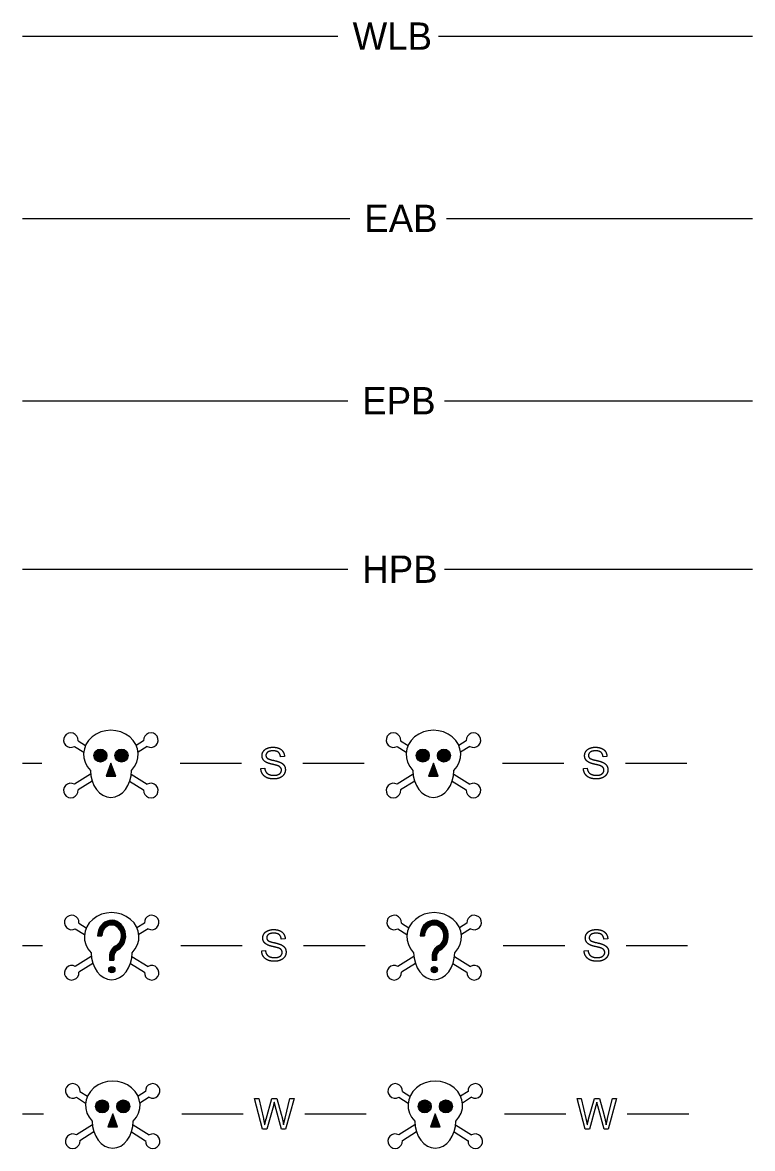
# Model space of a CAD drawing. Extents: x 811137 to 813186, y 647386 to 648494.
# Drawn here: x 811460.4 to 811541.1, y 647953.1 to 648077.7 of the extents above; entities that cross this region are included whole.
import ezdxf

# ---------------------------------------------------------------- set-up
doc = ezdxf.new("R2010")
doc.units = 0
doc.layers.add('Sheet_Symbology', color=7, linetype='Continuous')

msp = doc.modelspace()

# ---------------------------------------------------------------- linework, layer by layer
at = {"layer": 'Sheet_Symbology'}
for p, q in [((811460.36, 648076.23), (811495.24, 648076.23)), ((811506.34, 648076.23), (811541.07, 648076.23)), ((811460.36, 648056.06), (811496.54, 648056.06)), ((811507.23, 648056.06), (811541.07, 648056.06)), ((811460.36, 648035.88), (811496.31, 648035.88)), ((811507.01, 648035.88), (811541.07, 648035.88)), ((811460.36, 648017.25), (811496.31, 648017.25)), ((811507.01, 648017.25), (811541.07, 648017.25)), ((811466.51, 647998.26), (811467.33, 647997.74)), ((811473.75, 647998.26), (811472.93, 647997.74)), ((811502.17, 647998.26), (811503, 647997.74)), ((811509.41, 647998.26), (811508.59, 647997.74)), ((811466.1, 647997.62), (811467.12, 647996.98)), ((811474.15, 647997.62), (811473.13, 647996.98)), ((811501.77, 647997.62), (811502.79, 647996.98)), ((811509.82, 647997.62), (811508.8, 647996.98)), ((811460.36, 647995.78), (811462.48, 647995.78)), ((811477.77, 647995.78), (811484.56, 647995.78)), ((811489.32, 647996.52), (811488.89, 647996.49)), ((811491.36, 647995.78), (811498.15, 647995.78)), ((811513.44, 647995.78), (811520.23, 647995.78)), ((811524.98, 647996.52), (811524.55, 647996.49)), ((811527.02, 647995.78), (811533.82, 647995.78)), ((811467.88, 647994.57), (811466.1, 647993.45)), ((811470.13, 647995.53), (811470.13, 647995.53)), ((811472.38, 647994.57), (811474.15, 647993.45)), ((811486.71, 647995.18), (811487.14, 647995.21)), ((811503.55, 647994.57), (811501.77, 647993.45)), ((811505.79, 647995.53), (811505.79, 647995.53)), ((811508.04, 647994.57), (811509.82, 647993.45)), ((811522.38, 647995.18), (811522.8, 647995.21)), ((811468.05, 647993.78), (811466.51, 647992.81)), ((811472.2, 647993.78), (811473.75, 647992.81)), ((811503.72, 647993.78), (811502.17, 647992.81)), ((811507.87, 647993.78), (811509.41, 647992.81)), ((811466.19, 647977.44), (811467.2, 647976.8)), ((811466.59, 647978.08), (811467.41, 647977.56)), ((811473.83, 647978.08), (811473.01, 647977.56)), ((811474.24, 647977.44), (811473.22, 647976.8)), ((811501.85, 647977.44), (811502.87, 647976.8)), ((811502.26, 647978.08), (811503.08, 647977.56)), ((811509.5, 647978.08), (811508.67, 647977.56)), ((811509.9, 647977.44), (811508.88, 647976.8)), ((811468.65, 647976.66), (811469.13, 647976.66)), ((811489.4, 647976.35), (811488.97, 647976.31)), ((811504.32, 647976.66), (811504.8, 647976.66)), ((811525.07, 647976.35), (811524.64, 647976.31)), ((811460.36, 647975.6), (811462.57, 647975.6)), ((811470.21, 647975.6), (811470.21, 647975.6)), ((811477.85, 647975.6), (811484.65, 647975.6)), ((811486.8, 647975), (811487.22, 647975.03)), ((811491.44, 647975.6), (811498.23, 647975.6)), ((811505.88, 647975.6), (811505.88, 647975.6)), ((811513.52, 647975.6), (811520.31, 647975.6)), ((811522.46, 647975), (811522.89, 647975.03)), ((811527.11, 647975.6), (811533.9, 647975.6)), ((811467.96, 647974.39), (811466.19, 647973.27)), ((811468.13, 647973.6), (811466.59, 647972.63)), ((811469.97, 647974.38), (811469.97, 647973.96)), ((811469.97, 647973.96), (811470.45, 647973.96)), ((811470.04, 647974.38), (811470.04, 647973.96)), ((811470.11, 647974.38), (811470.11, 647973.96)), ((811470.18, 647974.38), (811470.18, 647973.96)), ((811470.25, 647974.38), (811470.25, 647973.96)), ((811470.31, 647974.38), (811470.31, 647973.96)), ((811470.38, 647974.38), (811470.38, 647973.96)), ((811470.45, 647974.38), (811470.45, 647973.96)), ((811472.29, 647973.6), (811473.83, 647972.63)), ((811472.46, 647974.39), (811474.24, 647973.27)), ((811503.63, 647974.39), (811501.85, 647973.27)), ((811503.8, 647973.6), (811502.26, 647972.63)), ((811505.64, 647974.38), (811505.64, 647973.96)), ((811505.64, 647973.96), (811506.12, 647973.96)), ((811505.7, 647974.38), (811505.7, 647973.96)), ((811505.77, 647974.38), (811505.77, 647973.96)), ((811505.84, 647974.38), (811505.84, 647973.96)), ((811505.91, 647974.38), (811505.91, 647973.96)), ((811505.98, 647974.38), (811505.98, 647973.96)), ((811506.05, 647974.38), (811506.05, 647973.96)), ((811506.12, 647974.38), (811506.12, 647973.96)), ((811507.95, 647973.6), (811509.5, 647972.63)), ((811508.12, 647974.39), (811509.9, 647973.27)), ((811466.31, 647958.8), (811467.32, 647958.16)), ((811466.71, 647959.44), (811467.53, 647958.92)), ((811473.95, 647959.44), (811473.13, 647958.92)), ((811474.35, 647958.8), (811473.34, 647958.16)), ((811501.97, 647958.8), (811502.99, 647958.16)), ((811502.37, 647959.44), (811503.2, 647958.92)), ((811509.62, 647959.44), (811508.79, 647958.92)), ((811510.02, 647958.8), (811509, 647958.16)), ((811460.36, 647956.96), (811462.69, 647956.96)), ((811477.97, 647956.96), (811484.77, 647956.96)), ((811491.56, 647956.96), (811498.35, 647956.96)), ((811513.64, 647956.96), (811520.43, 647956.96)), ((811527.23, 647956.96), (811534.02, 647956.96)), ((811468.08, 647955.75), (811466.31, 647954.64)), ((811470.33, 647956.72), (811470.33, 647956.72)), ((811472.58, 647955.75), (811474.35, 647954.64)), ((811503.75, 647955.75), (811501.97, 647954.64)), ((811506, 647956.72), (811506, 647956.72)), ((811508.24, 647955.75), (811510.02, 647954.64)), ((811468.25, 647954.97), (811466.71, 647953.99)), ((811472.41, 647954.97), (811473.95, 647953.99)), ((811503.92, 647954.97), (811502.37, 647953.99)), ((811508.07, 647954.97), (811509.62, 647953.99))]:
    msp.add_line(p, q, dxfattribs=at)
for points in [[(811470.13, 647995.78), (811469.6, 647994.33), (811470.66, 647994.33)], [(811505.79, 647995.78), (811505.26, 647994.33), (811506.33, 647994.33)], [(811470.13, 647995.53), (811469.72, 647994.41), (811470.54, 647994.41)], [(811470.13, 647995.29), (811469.84, 647994.5), (811470.42, 647994.5)], [(811470.13, 647995.04), (811469.96, 647994.58), (811470.29, 647994.58)], [(811470.13, 647994.79), (811470.08, 647994.67), (811470.17, 647994.67)], [(811505.79, 647995.53), (811505.38, 647994.41), (811506.2, 647994.41)], [(811505.79, 647995.29), (811505.5, 647994.5), (811506.08, 647994.5)], [(811505.79, 647995.04), (811505.63, 647994.58), (811505.96, 647994.58)], [(811505.79, 647994.79), (811505.75, 647994.67), (811505.84, 647994.67)], [(811470.33, 647956.96), (811469.8, 647955.51), (811470.86, 647955.51)], [(811506, 647956.96), (811505.46, 647955.51), (811506.53, 647955.51)], [(811470.33, 647956.72), (811469.92, 647955.6), (811470.74, 647955.6)], [(811470.33, 647956.47), (811470.04, 647955.68), (811470.62, 647955.68)], [(811470.33, 647956.22), (811470.16, 647955.77), (811470.5, 647955.77)], [(811470.33, 647955.98), (811470.28, 647955.85), (811470.38, 647955.85)], [(811506, 647956.72), (811505.59, 647955.6), (811506.41, 647955.6)], [(811506, 647956.47), (811505.71, 647955.68), (811506.29, 647955.68)], [(811506, 647956.22), (811505.83, 647955.77), (811506.16, 647955.77)], [(811506, 647955.98), (811505.95, 647955.85), (811506.04, 647955.85)]]:
    msp.add_lwpolyline(points, close=True, dxfattribs=at)
for points in [[(811488.09, 647957.85), (811487.37, 647955.27), (811486.91, 647955.27), (811486.01, 647958.66), (811486.47, 647958.66), (811486.99, 647956.44)], [(811487.28, 647956.37), (811487.93, 647958.66), (811488.47, 647958.66), (811488.96, 647956.94)], [(811489.39, 647956.48), (811489.92, 647958.66), (811490.38, 647958.66), (811489.45, 647955.27), (811489.01, 647955.27), (811488.3, 647957.86)], [(811523.75, 647957.85), (811523.04, 647955.27), (811522.58, 647955.27), (811521.67, 647958.66), (811522.13, 647958.66), (811522.65, 647956.44)], [(811522.95, 647956.37), (811523.6, 647958.66), (811524.14, 647958.66), (811524.62, 647956.94)], [(811525.06, 647956.48), (811525.59, 647958.66), (811526.04, 647958.66), (811525.11, 647955.27), (811524.68, 647955.27), (811523.96, 647957.86)]]:
    msp.add_lwpolyline(points, dxfattribs=at)
for centre, radius in [((811468.96, 647996.61), 0.72), ((811468.96, 647996.61), 0.635), ((811468.96, 647996.61), 0.55), ((811468.96, 647996.61), 0.465), ((811468.96, 647996.61), 0.38), ((811468.96, 647996.61), 0.295), ((811471.3, 647996.61), 0.72), ((811471.3, 647996.61), 0.635), ((811471.3, 647996.61), 0.55), ((811471.3, 647996.61), 0.465), ((811471.3, 647996.61), 0.38), ((811471.3, 647996.61), 0.295), ((811504.62, 647996.61), 0.72), ((811504.62, 647996.61), 0.635), ((811504.62, 647996.61), 0.55), ((811504.62, 647996.61), 0.465), ((811504.62, 647996.61), 0.38), ((811504.62, 647996.61), 0.295), ((811506.96, 647996.61), 0.72), ((811506.96, 647996.61), 0.635), ((811506.96, 647996.61), 0.55), ((811506.96, 647996.61), 0.465), ((811506.96, 647996.61), 0.38), ((811506.96, 647996.61), 0.295), ((811468.96, 647996.61), 0.211), ((811468.96, 647996.61), 0.126), ((811468.96, 647996.61), 0.0407), ((811471.3, 647996.61), 0.211), ((811471.3, 647996.61), 0.126), ((811471.3, 647996.61), 0.0407), ((811504.62, 647996.61), 0.211), ((811504.62, 647996.61), 0.126), ((811504.62, 647996.61), 0.0407), ((811506.96, 647996.61), 0.211), ((811506.96, 647996.61), 0.126), ((811506.96, 647996.61), 0.0407), ((811470.23, 647972.92), 0.344), ((811470.23, 647972.92), 0.267), ((811505.89, 647972.92), 0.344), ((811505.89, 647972.92), 0.267), ((811470.23, 647972.92), 0.19), ((811470.23, 647972.92), 0.113), ((811470.23, 647972.92), 0.0367), ((811505.89, 647972.92), 0.19), ((811505.89, 647972.92), 0.113), ((811505.89, 647972.92), 0.0367), ((811469.16, 647957.79), 0.72), ((811469.16, 647957.79), 0.635), ((811469.16, 647957.79), 0.55), ((811469.16, 647957.79), 0.465), ((811471.5, 647957.79), 0.72), ((811471.5, 647957.79), 0.635), ((811471.5, 647957.79), 0.55), ((811471.5, 647957.79), 0.465), ((811504.83, 647957.79), 0.72), ((811504.83, 647957.79), 0.635), ((811504.83, 647957.79), 0.55), ((811504.83, 647957.79), 0.465), ((811507.17, 647957.79), 0.72), ((811507.17, 647957.79), 0.635), ((811507.17, 647957.79), 0.55), ((811507.17, 647957.79), 0.465), ((811469.16, 647957.79), 0.38), ((811469.16, 647957.79), 0.295), ((811469.16, 647957.79), 0.211), ((811469.16, 647957.79), 0.126), ((811469.16, 647957.79), 0.0407), ((811471.5, 647957.79), 0.38), ((811471.5, 647957.79), 0.295), ((811471.5, 647957.79), 0.211), ((811471.5, 647957.79), 0.126), ((811471.5, 647957.79), 0.0407), ((811504.83, 647957.79), 0.38), ((811504.83, 647957.79), 0.295), ((811504.83, 647957.79), 0.211), ((811504.83, 647957.79), 0.126), ((811504.83, 647957.79), 0.0407), ((811507.17, 647957.79), 0.38), ((811507.17, 647957.79), 0.295), ((811507.17, 647957.79), 0.211), ((811507.17, 647957.79), 0.126), ((811507.17, 647957.79), 0.0407)]:
    msp.add_circle(centre, radius, dxfattribs=at)
for centre, start, end in [((811465.7, 647998.32), 355.8976, 299.8062), ((811474.55, 647998.32), 240.1938, 184.1024), ((811501.37, 647998.32), 355.8976, 299.8062), ((811510.22, 647998.32), 240.1938, 184.1024), ((811465.7, 647992.75), 60.1938, 4.1024), ((811474.55, 647992.75), 175.8976, 119.8062), ((811501.37, 647992.75), 60.1938, 4.1024), ((811510.22, 647992.75), 175.8976, 119.8062), ((811465.79, 647978.14), 355.8976, 299.8062), ((811474.64, 647978.14), 240.1938, 184.1024), ((811501.45, 647978.14), 355.8976, 299.8062), ((811510.3, 647978.14), 240.1938, 184.1024), ((811465.79, 647972.58), 60.1938, 4.1024), ((811474.64, 647972.58), 175.8976, 119.8062), ((811501.45, 647972.58), 60.1938, 4.1024), ((811510.3, 647972.58), 175.8976, 119.8062), ((811465.91, 647959.5), 355.8976, 299.8062), ((811474.75, 647959.5), 240.1938, 184.1024), ((811501.57, 647959.5), 355.8976, 299.8062), ((811510.42, 647959.5), 240.1938, 184.1024), ((811465.91, 647953.94), 60.1938, 4.1024), ((811474.75, 647953.94), 175.8976, 119.8062), ((811501.57, 647953.94), 60.1938, 4.1024), ((811510.42, 647953.94), 175.8976, 119.8062)]:
    msp.add_arc(centre, 0.805, start, end, dxfattribs=at)
for centre, major_axis, ratio, start_param, end_param in [((811470.13, 647996.74), (3.02, 0), 0.885014, 5.564242, 10.143721), ((811505.79, 647996.74), (3.02, 0), 0.885014, 5.564242, 10.143721), ((811470.13, 647995.01), (0, -3.02), 0.752542, 4.722735, 7.843636), ((811505.79, 647995.01), (0, -3.02), 0.752542, 4.722735, 7.843636), ((811470.21, 647976.56), (3.02, 0), 0.885014, 5.564242, 10.143721), ((811505.88, 647976.56), (3.02, 0), 0.885014, 5.564242, 10.143721), ((811470.21, 647976.66), (0, 1.73), 0.9, 3.567618, 7.853982), ((811470.21, 647976.66), (0, 1.66), 0.9, 3.567618, 7.853982), ((811470.21, 647976.66), (0, 1.58), 0.9, 3.567618, 7.853982), ((811470.21, 647976.66), (0, 1.5), 0.9, 3.567618, 7.853982), ((811470.21, 647976.66), (0, 1.43), 0.9, 3.567618, 7.853982), ((811505.88, 647976.66), (0, 1.73), 0.9, 3.567618, 7.853982), ((811505.88, 647976.66), (0, 1.66), 0.9, 3.567618, 7.853982), ((811505.88, 647976.66), (0, 1.58), 0.9, 3.567618, 7.853982), ((811505.88, 647976.66), (0, 1.5), 0.9, 3.567618, 7.853982), ((811505.88, 647976.66), (0, 1.43), 0.9, 3.567618, 7.853982), ((811470.21, 647976.66), (0, 1.35), 0.9, 3.567618, 7.853982), ((811470.21, 647976.66), (0, 1.27), 0.9, 3.567618, 7.853982), ((811470.21, 647976.66), (0, 1.2), 0.9, 3.567618, 7.853982), ((811505.88, 647976.66), (0, 1.35), 0.9, 3.567618, 7.853982), ((811505.88, 647976.66), (0, 1.27), 0.9, 3.567618, 7.853982), ((811505.88, 647976.66), (0, 1.2), 0.9, 3.567618, 7.853982), ((811470.21, 647974.83), (0, -3.02), 0.752542, 4.722735, 7.843636), ((811471.14, 647974.38), (0, 1.3), 0.9, 0.426026, 1.570796), ((811471.14, 647974.38), (0, 1.22), 0.9, 0.426026, 1.570796), ((811471.14, 647974.38), (0, 1.15), 0.9, 0.426026, 1.570796), ((811471.14, 647974.38), (0, 1.07), 0.9, 0.426026, 1.570796), ((811471.14, 647974.38), (0, 0.994), 0.9, 0.426026, 1.570796), ((811471.14, 647974.38), (0, 0.917), 0.9, 0.426026, 1.570796), ((811471.14, 647974.38), (0, 0.841), 0.9, 0.426026, 1.570796), ((811471.14, 647974.38), (0, 0.764), 0.9, 0.426026, 1.570796), ((811505.88, 647974.83), (0, -3.02), 0.752542, 4.722735, 7.843636), ((811506.81, 647974.38), (0, 1.3), 0.9, 0.426026, 1.570796), ((811506.81, 647974.38), (0, 1.22), 0.9, 0.426026, 1.570796), ((811506.81, 647974.38), (0, 1.15), 0.9, 0.426026, 1.570796), ((811506.81, 647974.38), (0, 1.07), 0.9, 0.426026, 1.570796), ((811506.81, 647974.38), (0, 0.994), 0.9, 0.426026, 1.570796), ((811506.81, 647974.38), (0, 0.917), 0.9, 0.426026, 1.570796), ((811506.81, 647974.38), (0, 0.841), 0.9, 0.426026, 1.570796), ((811506.81, 647974.38), (0, 0.764), 0.9, 0.426026, 1.570796), ((811470.33, 647957.92), (3.02, 0), 0.885014, 5.564242, 10.143721), ((811506, 647957.92), (3.02, 0), 0.885014, 5.564242, 10.143721), ((811470.33, 647956.19), (0, -3.02), 0.752542, 4.722735, 7.843636), ((811506, 647956.19), (0, -3.02), 0.752542, 4.722735, 7.843636)]:
    msp.add_ellipse(centre, major_axis=major_axis, ratio=ratio, start_param=start_param, end_param=end_param, dxfattribs=at)
for points in [[(811486.84, 647996.6), (811486.84, 647996.86), (811486.99, 647997.08)], [(811486.99, 647997.08), (811487.13, 647997.31), (811487.41, 647997.42)], [(811487.46, 647996.99), (811487.27, 647996.84), (811487.27, 647996.63)], [(811487.41, 647997.42), (811487.7, 647997.54), (811488.04, 647997.54)], [(811488.06, 647997.14), (811487.65, 647997.14), (811487.46, 647996.99)], [(811488.04, 647997.54), (811488.42, 647997.54), (811488.71, 647997.42)], [(811488.65, 647996.98), (811488.45, 647997.14), (811488.06, 647997.14)], [(811488.89, 647996.49), (811488.85, 647996.81), (811488.65, 647996.98)], [(811488.71, 647997.42), (811489, 647997.3), (811489.15, 647997.06)], [(811489.15, 647997.06), (811489.31, 647996.82), (811489.32, 647996.52)], [(811522.51, 647996.6), (811522.51, 647996.86), (811522.65, 647997.08)], [(811522.65, 647997.08), (811522.8, 647997.31), (811523.08, 647997.42)], [(811523.13, 647996.99), (811522.94, 647996.84), (811522.94, 647996.63)], [(811523.08, 647997.42), (811523.36, 647997.54), (811523.7, 647997.54)], [(811523.72, 647997.14), (811523.31, 647997.14), (811523.13, 647996.99)], [(811523.7, 647997.54), (811524.08, 647997.54), (811524.37, 647997.42)], [(811524.32, 647996.98), (811524.12, 647997.14), (811523.72, 647997.14)], [(811524.55, 647996.49), (811524.52, 647996.81), (811524.32, 647996.98)], [(811524.37, 647997.42), (811524.66, 647997.3), (811524.82, 647997.06)], [(811524.82, 647997.06), (811524.97, 647996.82), (811524.98, 647996.52)], [(811486.96, 647996.18), (811486.84, 647996.37), (811486.84, 647996.6)], [(811487.32, 647995.86), (811487.08, 647995.99), (811486.96, 647996.18)], [(811487.27, 647996.63), (811487.27, 647996.45), (811487.41, 647996.33)], [(811487.98, 647995.65), (811487.51, 647995.76), (811487.32, 647995.86)], [(811487.41, 647996.33), (811487.54, 647996.21), (811488.09, 647996.09)], [(811488.59, 647995.49), (811488.45, 647995.54), (811487.98, 647995.65)], [(811488.09, 647996.09), (811488.64, 647995.97), (811488.84, 647995.87)], [(811488.84, 647995.87), (811489.14, 647995.74), (811489.28, 647995.53)], [(811522.63, 647996.18), (811522.51, 647996.37), (811522.51, 647996.6)], [(811522.99, 647995.86), (811522.75, 647995.99), (811522.63, 647996.18)], [(811522.94, 647996.63), (811522.94, 647996.45), (811523.07, 647996.33)], [(811523.65, 647995.65), (811523.18, 647995.76), (811522.99, 647995.86)], [(811523.07, 647996.33), (811523.2, 647996.21), (811523.75, 647996.09)], [(811524.25, 647995.49), (811524.12, 647995.54), (811523.65, 647995.65)], [(811523.75, 647996.09), (811524.3, 647995.97), (811524.51, 647995.87)], [(811524.51, 647995.87), (811524.8, 647995.74), (811524.94, 647995.53)], [(811486.9, 647994.57), (811486.72, 647994.83), (811486.71, 647995.18)], [(811487.39, 647994.16), (811487.08, 647994.3), (811486.9, 647994.57)], [(811487.14, 647995.21), (811487.17, 647994.96), (811487.28, 647994.79)], [(811487.28, 647994.79), (811487.39, 647994.63), (811487.62, 647994.53)], [(811487.62, 647994.53), (811487.85, 647994.43), (811488.14, 647994.43)], [(811488.14, 647994.43), (811488.4, 647994.43), (811488.6, 647994.5)], [(811488.89, 647995.28), (811488.8, 647995.4), (811488.59, 647995.49)], [(811488.6, 647994.5), (811488.79, 647994.58), (811488.89, 647994.71)], [(811489.26, 647994.53), (811489.11, 647994.29), (811488.82, 647994.16)], [(811488.99, 647995.01), (811488.99, 647995.17), (811488.89, 647995.28)], [(811488.89, 647994.71), (811488.99, 647994.85), (811488.99, 647995.01)], [(811489.42, 647995.04), (811489.42, 647994.77), (811489.26, 647994.53)], [(811489.28, 647995.53), (811489.42, 647995.32), (811489.42, 647995.04)], [(811522.57, 647994.57), (811522.39, 647994.83), (811522.38, 647995.18)], [(811523.06, 647994.16), (811522.74, 647994.3), (811522.57, 647994.57)], [(811522.8, 647995.21), (811522.83, 647994.96), (811522.94, 647994.79)], [(811522.94, 647994.79), (811523.05, 647994.63), (811523.29, 647994.53)], [(811523.29, 647994.53), (811523.52, 647994.43), (811523.81, 647994.43)], [(811523.81, 647994.43), (811524.07, 647994.43), (811524.26, 647994.5)], [(811524.56, 647995.28), (811524.47, 647995.4), (811524.25, 647995.49)], [(811524.26, 647994.5), (811524.46, 647994.58), (811524.56, 647994.71)], [(811524.93, 647994.53), (811524.77, 647994.29), (811524.48, 647994.16)], [(811524.65, 647995.01), (811524.65, 647995.17), (811524.56, 647995.28)], [(811524.56, 647994.71), (811524.65, 647994.85), (811524.65, 647995.01)], [(811525.09, 647995.04), (811525.09, 647994.77), (811524.93, 647994.53)], [(811524.94, 647995.53), (811525.09, 647995.32), (811525.09, 647995.04)], [(811488.16, 647994.03), (811487.7, 647994.03), (811487.39, 647994.16)], [(811488.82, 647994.16), (811488.53, 647994.03), (811488.16, 647994.03)], [(811523.83, 647994.03), (811523.37, 647994.03), (811523.06, 647994.16)], [(811524.48, 647994.16), (811524.19, 647994.03), (811523.83, 647994.03)], [(811486.92, 647976.42), (811486.92, 647976.68), (811487.07, 647976.91)], [(811487.07, 647976.91), (811487.22, 647977.13), (811487.5, 647977.24)], [(811487.5, 647977.24), (811487.78, 647977.36), (811488.12, 647977.36)], [(811488.14, 647976.96), (811487.73, 647976.96), (811487.54, 647976.81)], [(811488.12, 647977.36), (811488.5, 647977.36), (811488.79, 647977.24)], [(811488.74, 647976.8), (811488.53, 647976.96), (811488.14, 647976.96)], [(811488.79, 647977.24), (811489.08, 647977.12), (811489.23, 647976.88)], [(811522.59, 647976.42), (811522.59, 647976.68), (811522.74, 647976.91)], [(811522.74, 647976.91), (811522.88, 647977.13), (811523.16, 647977.24)], [(811523.16, 647977.24), (811523.44, 647977.36), (811523.79, 647977.36)], [(811523.81, 647976.96), (811523.4, 647976.96), (811523.21, 647976.81)], [(811523.79, 647977.36), (811524.17, 647977.36), (811524.46, 647977.24)], [(811524.4, 647976.8), (811524.2, 647976.96), (811523.81, 647976.96)], [(811524.46, 647977.24), (811524.74, 647977.12), (811524.9, 647976.88)], [(811487.04, 647976), (811486.92, 647976.19), (811486.92, 647976.42)], [(811487.41, 647975.68), (811487.16, 647975.81), (811487.04, 647976)], [(811487.54, 647976.81), (811487.36, 647976.67), (811487.36, 647976.45)], [(811487.36, 647976.45), (811487.36, 647976.27), (811487.49, 647976.15)], [(811488.06, 647975.47), (811487.59, 647975.58), (811487.41, 647975.68)], [(811487.49, 647976.15), (811487.62, 647976.03), (811488.17, 647975.91)], [(811488.17, 647975.91), (811488.72, 647975.79), (811488.92, 647975.69)], [(811488.97, 647976.31), (811488.94, 647976.63), (811488.74, 647976.8)], [(811488.92, 647975.69), (811489.22, 647975.56), (811489.36, 647975.35)], [(811489.23, 647976.88), (811489.39, 647976.64), (811489.4, 647976.35)], [(811522.71, 647976), (811522.59, 647976.19), (811522.59, 647976.42)], [(811523.07, 647975.68), (811522.83, 647975.81), (811522.71, 647976)], [(811523.21, 647976.81), (811523.02, 647976.67), (811523.02, 647976.45)], [(811523.02, 647976.45), (811523.02, 647976.27), (811523.16, 647976.15)], [(811523.73, 647975.47), (811523.26, 647975.58), (811523.07, 647975.68)], [(811523.16, 647976.15), (811523.29, 647976.03), (811523.84, 647975.91)], [(811523.84, 647975.91), (811524.39, 647975.79), (811524.59, 647975.69)], [(811524.64, 647976.31), (811524.6, 647976.63), (811524.4, 647976.8)], [(811524.59, 647975.69), (811524.89, 647975.56), (811525.03, 647975.35)], [(811524.9, 647976.88), (811525.06, 647976.64), (811525.07, 647976.35)], [(811486.98, 647974.39), (811486.81, 647974.66), (811486.8, 647975)], [(811487.22, 647975.03), (811487.25, 647974.78), (811487.36, 647974.61)], [(811487.36, 647974.61), (811487.47, 647974.45), (811487.7, 647974.35)], [(811488.67, 647975.31), (811488.53, 647975.36), (811488.06, 647975.47)], [(811488.98, 647975.11), (811488.89, 647975.23), (811488.67, 647975.31)], [(811488.68, 647974.33), (811488.88, 647974.4), (811488.97, 647974.54)], [(811488.97, 647974.54), (811489.07, 647974.67), (811489.07, 647974.83)], [(811489.07, 647974.83), (811489.07, 647974.99), (811488.98, 647975.11)], [(811489.5, 647974.86), (811489.5, 647974.59), (811489.35, 647974.35)], [(811489.36, 647975.35), (811489.5, 647975.14), (811489.5, 647974.86)], [(811522.65, 647974.39), (811522.47, 647974.66), (811522.46, 647975)], [(811522.89, 647975.03), (811522.92, 647974.78), (811523.03, 647974.61)], [(811523.03, 647974.61), (811523.14, 647974.45), (811523.37, 647974.35)], [(811524.34, 647975.31), (811524.2, 647975.36), (811523.73, 647975.47)], [(811524.64, 647975.11), (811524.55, 647975.23), (811524.34, 647975.31)], [(811524.35, 647974.33), (811524.54, 647974.4), (811524.64, 647974.54)], [(811524.74, 647974.83), (811524.74, 647974.99), (811524.64, 647975.11)], [(811524.64, 647974.54), (811524.74, 647974.67), (811524.74, 647974.83)], [(811525.17, 647974.86), (811525.17, 647974.59), (811525.01, 647974.35)], [(811525.03, 647975.35), (811525.17, 647975.14), (811525.17, 647974.86)], [(811487.47, 647973.98), (811487.16, 647974.12), (811486.98, 647974.39)], [(811488.25, 647973.85), (811487.78, 647973.85), (811487.47, 647973.98)], [(811487.7, 647974.35), (811487.94, 647974.25), (811488.23, 647974.25)], [(811488.23, 647974.25), (811488.48, 647974.25), (811488.68, 647974.33)], [(811488.9, 647973.98), (811488.61, 647973.85), (811488.25, 647973.85)], [(811489.35, 647974.35), (811489.19, 647974.11), (811488.9, 647973.98)], [(811523.14, 647973.98), (811522.83, 647974.12), (811522.65, 647974.39)], [(811523.91, 647973.85), (811523.45, 647973.85), (811523.14, 647973.98)], [(811523.37, 647974.35), (811523.6, 647974.25), (811523.89, 647974.25)], [(811523.89, 647974.25), (811524.15, 647974.25), (811524.35, 647974.33)], [(811524.57, 647973.98), (811524.28, 647973.85), (811523.91, 647973.85)], [(811525.01, 647974.35), (811524.86, 647974.11), (811524.57, 647973.98)], [(811488.19, 647958.25), (811488.13, 647958.02), (811488.09, 647957.85)], [(811488.3, 647957.86), (811488.21, 647958.18), (811488.19, 647958.25)], [(811523.86, 647958.25), (811523.8, 647958.02), (811523.75, 647957.85)], [(811523.96, 647957.86), (811523.87, 647958.18), (811523.86, 647958.25)], [(811486.99, 647956.44), (811487.07, 647956.09), (811487.13, 647955.74)], [(811487.13, 647955.74), (811487.26, 647956.29), (811487.28, 647956.37)], [(811488.96, 647956.94), (811489.14, 647956.3), (811489.22, 647955.74)], [(811489.22, 647955.74), (811489.29, 647956.06), (811489.39, 647956.48)], [(811522.65, 647956.44), (811522.74, 647956.09), (811522.8, 647955.74)], [(811522.8, 647955.74), (811522.93, 647956.29), (811522.95, 647956.37)], [(811524.62, 647956.94), (811524.81, 647956.3), (811524.89, 647955.74)], [(811524.89, 647955.74), (811524.95, 647956.06), (811525.06, 647956.48)]]:
    msp.add_open_spline(points, degree=2, dxfattribs=at)

# ---------------------------------------------------------------- texts
for s, p in [('WLB', (811496.86, 648074.72)), ('EAB', (811498.15, 648054.55)), ('EPB', (811497.93, 648034.37)), ('HPB', (811497.93, 648015.73))]:
    msp.add_text(s, height=3.027, dxfattribs=at).set_placement(p)

doc.saveas('drawing.dxf')
